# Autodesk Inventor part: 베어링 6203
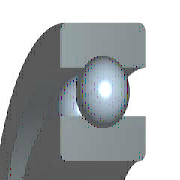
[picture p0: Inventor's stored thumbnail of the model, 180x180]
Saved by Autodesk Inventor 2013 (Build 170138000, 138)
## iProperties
IsCustomPart: 1
Company: 한국ATC센터
Created: 2009-02
Part Number: 베어링 6203
Material: 강, 연강
Description: 깊은 그루브 볼 베어링
Document SubType Name: Modeling
Standard: KS B 2023
Designer: KYOUNG IL JANG
Standards Organization: KS
Language: ko-KR
Size Designation: 6203 - 17 x 40 x 12
Categories: <MemberInstance><Categories><Category DisplayName="샤프트 부품" InternalName="7f7aeb1f-a693-4053-b835-cee3144e0d98" Mnemonic="SHFT"><Category DisplayName="베어링" Inter
Density: 1 g/cm^3
Author: KYOUNG IL JANG
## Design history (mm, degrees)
sketch "스케치" dims "d0" = 5.98 (= -0.26 x WD + 0.26 x BD)
  geometry: L1 (3.01, 14.25)-(8.99, 14.25); L2 (6, 14.25)-(6, 11.26); L3 (6, 14.25)-(6, 17.24); L4 (3.778, 12.249)-(0, 12.249); L5 (0, 8.5)-(12, 8.5); L6 (3.778, 16.251)-(0, 16.251); L7 (0, 20)-(12, 20); L8 (12, 8.5)-(12, 12.249); L9 (8.222, 12.249)-(12, 12.249); L10 (8.222, 16.251)-(12, 16.251); L11 (12, 20)-(12, 16.251); L12 (-1.4, 0)-(8.4, 0) reference; L13 (0, -0.3)-(0, 5.3) reference
  constraints: 22 end point, 4 point on line, 2 collinear, 2 perpendicular, 2 symmetric about line, 1 midpoint, 1 parallel, 14 other
  dimensions: "d9" = 17 diameter of L5 L12 (= WD); "d11" = 40 diameter of L7 L12 (= BD); "d12" = 12 distance between parallel lines of L8 L13 (= KB); "d13" = 24.498 diameter of L9 L12 (= 0.326 x BD + 0.674 x WD)
revolve "본체" stored, may be unused: angle "d6" = 90 deg
revolve "볼" stored, may be unused: angle "d7" = 90 deg
pattern_circular "IDS_ARRAYBALL[SIMPL:T]" dims angle "d3" = 360 deg
body "Solid1"
fillet "모깎기1" dims "d1" = 0.6 (= KRS)
other parameters: "WD" = 17 [user parameter; used in 5 equation terms], "BD" = 40 [user parameter; used in 5 equation terms], "KB" = 12 [user parameter; used in 1 equation term], "KRS" = 0.6 [user parameter; used in 1 equation term], "d4" = 0, "d5" = 0, "d8" = 0, "d14" = 0, "d15" = 0, "BBA" = 0 [user parameter], "BC0" = 4750000 [user parameter], "BC" = 9560000 [user parameter], "WR" = 8.5 (= 0.5 x WD) [user parameter]
